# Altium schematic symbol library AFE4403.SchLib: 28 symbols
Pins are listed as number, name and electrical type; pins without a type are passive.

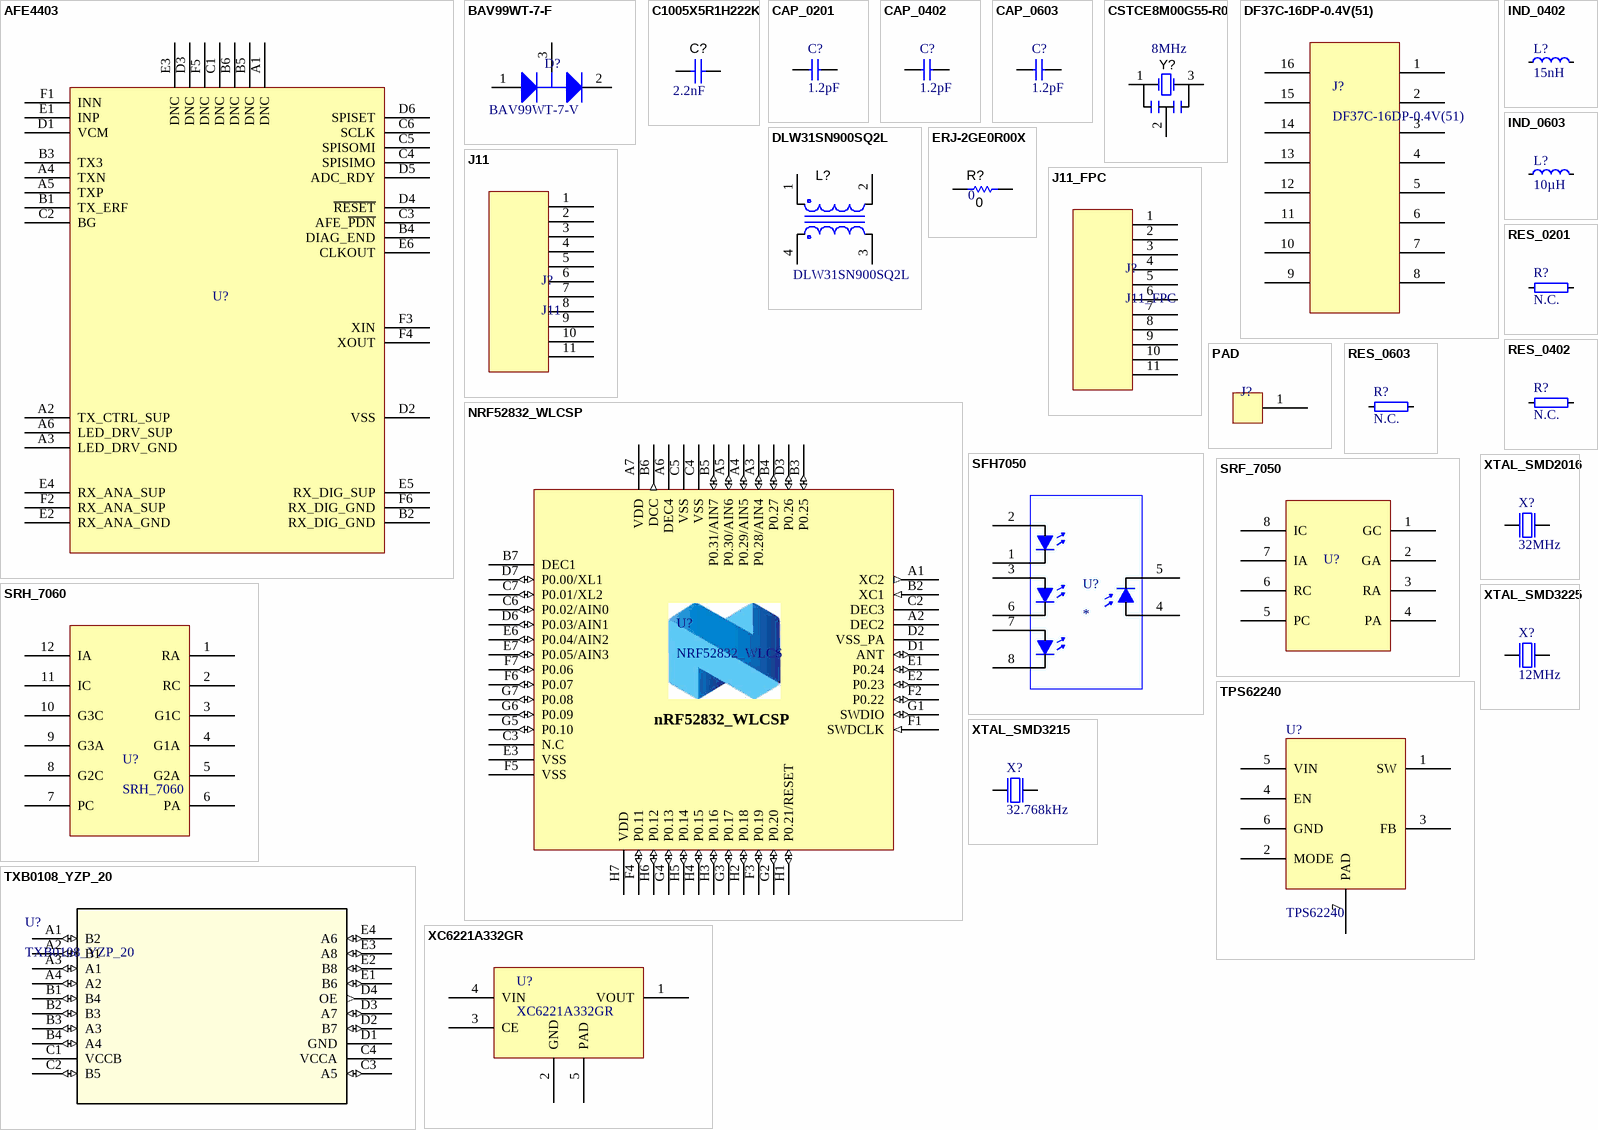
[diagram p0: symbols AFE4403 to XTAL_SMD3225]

## AFE4403
designator U?  (value not drawn)
pins: A1 DNC, A2 TX_CTRL_SUP, A3 LED_DRV_GND, A4 TXN, A5 TXP, A6 LED_DRV_SUP, B1 TX_ERF, B2 RX_DIG_GND, B3 TX3, B4 DIAG_END, B5 DNC, B6 DNC, C1 DNC, C2 BG, C3 AFE_~{PDN}, C4 SPISIMO, C5 SPISOMI, C6 SCLK, D1 VCM, D2 VSS, D3 DNC, D4 ~{RESET}, D5 ADC_RDY, D6 SPISET, E1 INP, E2 RX_ANA_GND, E3 DNC, E4 RX_ANA_SUP, E5 RX_DIG_SUP, E6 CLKOUT, F1 INN, F2 RX_ANA_SUP, F3 XIN, F4 XOUT, F5 DNC, F6 RX_DIG_GND

## BAV99WT-7-F
designator D?  Name: BAV99WT-7-V
DIODE, DUAL SWITCHING DIODE,  0.215A, 75V, SOT-323
footprint SOT-323
pins: 1 A, 2 C, 3 A_C

## C1005X5R1H222K
designator C?  value 2.2nF  (hidden comment: C1005X5R1H222K)
CAP, CERAMIC, 2.2NF, 10%, 50V, X5R, SMT0402; MANUFACTURER: TDK; POPULATE: Y; CONSIGNED: N
footprint 0402
pins: 1, 2

## CAP_0201
designator C?, comment 1.2pF
Capacitor, NP0, ±0.1pF; Part Number: C0201-1.2p; Note: 50V; Artikkelnr Noca: 20029157; Artikkelnr Simpro: N.A.
footprint 0201
pins: 1, 2

## CAP_0402
designator C?, comment 1.2pF
Capacitor, NP0, ±0.1pF; Part Number: C0402-1.2p; Note: 50V; Artikkelnr Noca: 20029157; Artikkelnr Simpro: N.A.
footprint 0402
pins: 1, 2

## CAP_0603
designator C?, comment 1.2pF
Capacitor, NP0, ±0.1pF; Part Number: C0603-1.2p; Note: 50V; Artikkelnr Noca: 20029157; Artikkelnr Simpro: N.A.
footprint 0603
pins: 1, 2

## CSTCE8M00G55-R0
designator Y?  value 8MHz
CRYSTAL, PIEZO CERAMIC RESONATOR, 8.00 MHz, SMD, 0.5%, 33pF, SMD; MANUFACTURER: MURATA; PART NUMBER: CSTCE8M00G55-R0; POPULATE: Y; CONSIGNED: N
footprint RESONATOR-1.3X3.2-MURATA
pins: 1, 2, 3

## DF37C-16DP-0.4V(51)
designator J?
footprint DF37C-16DP-0.4V(51)
pins: 1, 2, 3, 4, 5, 6, 7, 8, 9, 10, 11, 12, 13, 14, 15, 16

## DLW31SN900SQ2L
designator L?  value DLW31SN900SQ2L
INDUCTOR, CHOKE COIL WIRE WOUND, 0.37A, SMT1206, 4-PIN; MANUFACTURER: MURATA; POPULATE: Y; CONSIGNED: N
footprint IND_1206-4P
pins: 1, 2, 3, 4

## ERJ-2GE0R00X
designator R?, comment 0
RESISTOR, THICK FILM, 0, JUMPER, 0.1W, SMT0402; PART NUMBER: ERJ-2GE0R00X; MANUFACTURER: PANASONIC; POPULATE: N
footprint 0402
pins: 1, 2

## IND_0402
designator L?, comment 15nH
Inductor, 320mA, ±5%; Part Number: L0402-15n; Manufacturer: Taiyo Yuden; Manufacturer Part Number: HK100515NJ-T; 2nd source part number: 658-1328; Note: High frequency chip inductor ±10%; Artikkelnr Noca: 33029323; Artikkelnr Simpro: N.A.
footprint INDC1005X04L
pins: 1, 2

## IND_0603
designator L?, comment 10µH
Inductor, 80mA, ±10%; Part Number: L0603-10µ; Manufacturer: Taiyo Yuden; Manufacturer Part Number: LBMF1608T100K; 2nd source part number: 178-6105; Note: LBMF1608T100K 10µH 80mA 0603; Artikkelnr Noca: 33029314; Artikkelnr Simpro: N.A.
footprint INDC1608X06L
pins: 1, 2

## J11
designator J?
footprint J11
pins: 1, 2, 3, 4, 5, 6, 7, 8, 9, 10, 11

## J11_FPC
designator J?
footprint J11_FPC
pins: 1, 2, 3, 4, 5, 6, 7, 8, 9, 10, 11

## NRF52832_WLCSP
designator U?, comment NRF52832_WLCS
pins: A1 XC2 (out), A2 DEC2 (power), A3 P0.28/AIN4 (io), A4 P0.29/AIN5 (io), A5 P0.30/AIN6 (io), A6 DEC4 (power), A7 VDD (power), B2 XC1 (in), B3 P0.25 (io), B4 P0.27 (io), B5 P0.31/AIN7 (io), B6 DCC (out), B7 DEC1 (power), C2 DEC3 (power), C3 N.C, C4 VSS (power), C5 VSS (power), C6 P0.02/AIN0 (io), C7 P0.01/XL2 (io), D1 ANT (io), D2 VSS_PA (power), D3 P0.26 (io), D6 P0.03/AIN1 (io), D7 P0.00/XL1 (io), E1 P0.24 (io), E2 P0.23 (io), E3 VSS, E6 P0.04/AIN2 (io), E7 P0.05/AIN3 (io), F1 SWDCLK (in), F2 P0.22 (io), F3 P0.19 (io), F4 P0.11 (io), F5 VSS, F6 P0.07 (io), F7 P0.06 (io), G1 SWDIO (io), G2 P0.20 (io), G3 P0.17 (io), G4 P0.13 (io), G5 P0.10 (io), G6 P0.09 (io), G7 P0.08 (io), H1 P0.21/RESET (io), H2 P0.18 (io), H3 P0.16 (io), H4 P0.15 (io), H5 P0.14 (io), H6 P0.12 (io), H7 VDD (power)

## PAD
designator J?
footprint PAD1.5
pins: 1 PAD

## RES_0201
designator R?, comment N.C.
Not mounted; Part Number: R0201-N.C.; Note: Chip Res; Artikkelnr Noca: N.A.
footprint 0201
pins: 1, 2

## RES_0402
designator R?, comment N.C.
Not mounted; Part Number: R0402-N.C.; Note: Chip Res; Artikkelnr Noca: N.A.
footprint 0402
pins: 1, 2

## RES_0603
designator R?, comment N.C.
Not mounted; Part Number: R0603-N.C.; Note: Chip Res; Artikkelnr Noca: N.A.
footprint 0603
pins: 1, 2

## SFH7050
designator U?
footprint SFH7050
pins: 1, 2, 3, 4, 5, 6, 7, 8

## SRF_7050
designator U?  (value not drawn)
pins: 1 GC, 2 GA, 3 RA, 4 PA, 5 PC, 6 RC, 7 IA, 8 IC

## SRH_7060
designator U?
footprint SRH_7060
pins: 1 RA, 2 RC, 3 G1C, 4 G1A, 5 G2A, 6 PA, 7 PC, 8 G2C, 9 G3A, 10 G3C, 11 IC, 12 IA

## TPS62240
designator U?
pins: 1 SW, 2 MODE, 3 FB, 4 EN, 5 VIN, 6 GND, 7 PAD

## TXB0108_YZP_20
designator U?
Imported; Vendor: Texas Instruments; PACKAGE_DESIGNATOR: YZP; PIN_COUNT: 20; FAMILY_NAME: AUTO DIRECTION SENSING DUAL SUPPLY TRANSLATOR; INDUSTRY_STD_PKG_TYPE: DSBGA
footprint BGA20C50P4X5_189X239X50 (BGA, 20-Leads, Body 1.89x2.39mmx0.50mm, Pitch 0.50mm)
pins: A1 B2 (io), A2 B1 (io), A3 A1 (io), A4 A2 (io), B1 B4 (io), B2 B3 (io), B3 A3 (io), B4 A4 (io), C1 VCCB (power), C2 B5 (io), C3 A5 (io), C4 VCCA (power), D1 GND (power), D2 B7 (io), D3 A7 (io), D4 OE (out), E1 B6 (io), E2 B8 (io), E3 A8 (io), E4 A6 (io)

## XC6221A332GR
designator U?
footprint USP-4
pins: 1 VOUT, 2 GND, 3 CE, 4 VIN, 5 PAD

## XTAL_SMD2016
designator X?, comment 32MHz
XTAL SMD 2016, 32MHz, Cl=8pF, Tol: ±10ppm, Stab: ±10ppm; Part Number: XTAL_SMD2016_32MHz_8pF_Epson; Manufacturer: Epson Toyocom; Manufacturer Part Number: Q22FA12800025; Note: XTAL SMD 32.000MHz; Artikkelnr Noca: N.A.
footprint BT-XTAL_2016
pins: 1 inp, 2 GND hidden to GND, 3 out, 4 GND hidden to GND

## XTAL_SMD3215
designator X?, comment 32.768kHz
EPSON TOYOCOM - FC-135 32.768KHZ ±20PPM,9.0PF - CRYSTAL, SM, WATCH; Part Number: XTAL_FC-135 32.768k; 2nd source part number: 127-8037; Note: XTAL SMD 32.768kHz, 3215; Artikkelnr Noca: 22019091; Artikkelnr Simpro: N.A.
footprint XTAL_3215
pins: 1 inp, 2 out

## XTAL_SMD3225
designator X?, comment 12MHz
XTAL SMD 3225, 12MHz, 18pF, ±30ppm; Part Number: XTAL SMD 12MHz (3225); Manufacturer: TXC Corporation; Manufacturer Part Number: 7M-12.000MAAJ-T; 2nd source part number: 184-2056; Note: XTAL SMD 12.000MHz; Artikkelnr Noca: 22019166; Artikkelnr Simpro: N.A.
footprint BT-XTAL_3225
pins: 1 inp, 2 GND hidden to GND, 3 out, 4 GND hidden to GND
